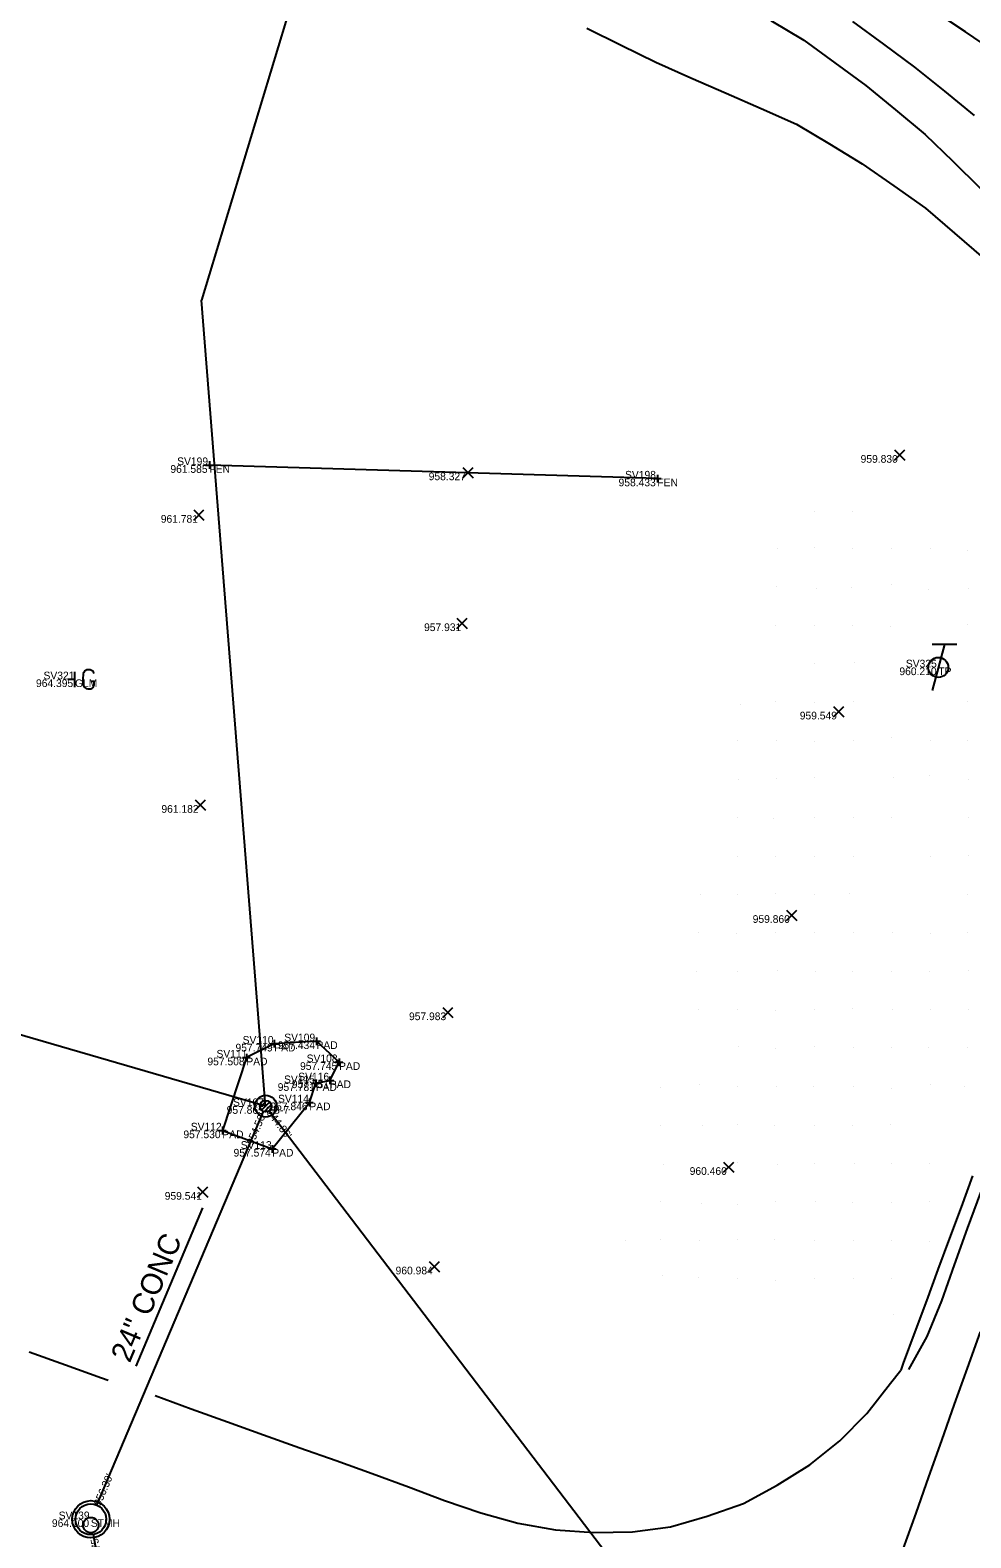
# Model space of a CAD drawing. Extents: x 2262025 to 2264532, y 740981 to 742724.
# Drawn here: x 2262920.9 to 2263043.2, y 741598.2 to 741794.3 of the extents above; entities that cross this region are included whole.
import ezdxf

# ---------------------------------------------------------------- set-up
doc = ezdxf.new("R2010")
doc.units = 0
for name, color, linetype in [('DR_X_Storm_Sewer', 7, 'Continuous'), ('DR_X_Text', 7, 'Continuous'), ('DT_X_Break_Line', 7, 'Continuous'), ('GE_X_Alignment_1000_Cardinal_Points', 7, 'Continuous'), ('GE_X_Alignment_100_Curve_Data', 7, 'Continuous'), ('GE_X_Alignment_500_Bearings', 7, 'Continuous'), ('GE_X_Alignment_500_Cardinal_Points', 7, 'Continuous'), ('Ground Shots', 7, 'Continuous'), ('HY_X_Spring_Cells', 7, 'Continuous'), ('RS_Raster1', 7, 'Continuous'), ('RW_X_CL', 7, 'Continuous'), ('RW_X_CL_1000_Distances', 7, 'Continuous'), ('RW_X_CL_100_Cardinal_Points', 7, 'Continuous'), ('RW_X_CL_100_Curve_Data', 7, 'Continuous'), ('RW_X_CL_100_Stations', 7, 'Continuous'), ('RW_X_CL_500_Curve_Data', 7, 'Continuous'), ('RW_X_CL_500_Stations', 7, 'Continuous'), ('SV_X_Control_Cells_Found', 7, 'Continuous'), ('SV_X_Text_Comment', 7, 'Continuous'), ('UT_X_Gas_Cells', 7, 'Continuous'), ('UT_X_Telecom_Cells', 7, 'Continuous')]:
    doc.layers.add(name, color=color, linetype=linetype)

msp = doc.modelspace()

# ---------------------------------------------------------------- linework, layer by layer
at = {"layer": 'DR_X_Storm_Sewer'}
for p, q in [((2262952, 741653.76), (2263353.07, 741127.49)), ((2262929.6, 741602.48), (2262951.25, 741653.67)), ((2262938.08, 741547.02), (2262929.17, 741598.66))]:
    msp.add_line(p, q, dxfattribs=at)
at = {"layer": 'DR_X_Text'}
msp.add_line((2262943.35, 741641.14), (2262934.65, 741620.56), dxfattribs=at)
at = {"layer": 'DT_X_Break_Line'}
msp.add_lwpolyline([(2263092.31, 741760.6), (2263084, 741766.16), (2263075.69, 741771.72), (2263067.37, 741777.28), (2263059.06, 741782.84), (2263050.77, 741788.43), (2263042.51, 741794.07), (2263034.2, 741799.62), (2263026.31, 741804.81)], dxfattribs=at)
at = {"layer": 'GE_X_Alignment_1000_Cardinal_Points'}
msp.add_lwpolyline([(2263002.45, 741735.97), (2262944.23, 741737.72)], dxfattribs=at)
at = {"layer": 'GE_X_Alignment_100_Curve_Data'}
for points in [[(2263017.19, 741795.56), (2263021.47, 741792.98), (2263025.51, 741790.04), (2263029.55, 741787.09), (2263033.41, 741783.91), (2263037.27, 741780.73), (2263040.85, 741777.24), (2263044.42, 741773.74)], [(2263044.43, 741643.14), (2263042.71, 741638.45), (2263041.05, 741633.73), (2263039.37, 741629.03), (2263037.49, 741624.39), (2263035.11, 741620.09)]]:
    msp.add_lwpolyline(points, dxfattribs=at)
at = {"layer": 'GE_X_Alignment_500_Bearings'}
for points in [[(2262920.8, 741622.42), (2262925.51, 741620.73), (2262930.21, 741619.04), (2262931.07, 741618.73)], [(2262937.16, 741616.72), (2262941.86, 741615.01), (2262946.56, 741613.3), (2262951.26, 741611.59), (2262955.98, 741609.93), (2262960.7, 741608.29), (2262965.4, 741606.6), (2262970.09, 741604.85), (2262974.77, 741603.09), (2262979.49, 741601.45), (2262984.3, 741600.11), (2262989.22, 741599.25), (2262994.2, 741598.92), (2262999.2, 741598.99), (2263004.15, 741599.63), (2263008.94, 741601.03), (2263013.64, 741602.69), (2263018.03, 741605.08), (2263022.27, 741607.72), (2263026.18, 741610.82), (2263029.67, 741614.38), (2263032.75, 741618.32), (2263034.09, 741620.03)]]:
    msp.add_lwpolyline(points, dxfattribs=at)
at = {"layer": 'GE_X_Alignment_500_Cardinal_Points'}
for p, q in [((2263033.26, 741738.36), (2263034.6, 741739.7)), ((2263033.26, 741739.7), (2263034.6, 741738.36)), ((2262977.17, 741736.09), (2262978.5, 741737.43)), ((2262977.17, 741737.43), (2262978.5, 741736.09)), ((2262942.19, 741730.56), (2262943.52, 741731.9)), ((2262942.19, 741731.9), (2262943.52, 741730.56)), ((2262976.4, 741716.48), (2262977.74, 741717.81)), ((2262976.4, 741717.81), (2262977.74, 741716.48)), ((2263025.33, 741704.98), (2263026.67, 741706.32)), ((2263025.33, 741706.32), (2263026.67, 741704.98)), ((2262942.38, 741692.85), (2262943.71, 741694.18)), ((2262942.38, 741694.18), (2262943.71, 741692.85)), ((2263019.23, 741678.52), (2263020.56, 741679.85)), ((2263019.23, 741679.85), (2263020.56, 741678.52)), ((2262974.56, 741665.87), (2262975.89, 741667.2)), ((2262974.56, 741667.2), (2262975.89, 741665.87)), ((2263011.05, 741645.75), (2263012.38, 741647.08)), ((2263011.05, 741647.08), (2263012.38, 741645.75)), ((2262942.7, 741642.52), (2262944.03, 741643.86)), ((2262942.7, 741643.86), (2262944.03, 741642.52)), ((2262972.8, 741632.82), (2262974.13, 741634.15)), ((2262972.8, 741634.15), (2262974.13, 741632.82))]:
    msp.add_line(p, q, dxfattribs=at)
at = {"layer": 'Ground Shots'}
for p, q in [((2263022.82, 741731.73), (2263022.82, 741731.73)), ((2263027.75, 741731.74), (2263027.75, 741731.74)), ((2263018.03, 741726.82), (2263018.03, 741726.82)), ((2263022.85, 741727), (2263022.85, 741727)), ((2263027.78, 741726.88), (2263027.78, 741726.88)), ((2263032.83, 741726.94), (2263032.83, 741726.94)), ((2263037.9, 741726.86), (2263037.9, 741726.86)), ((2263042.82, 741726.62), (2263042.82, 741726.62)), ((2263017.94, 741721.96), (2263017.94, 741721.96)), ((2263023.09, 741721.68), (2263023.09, 741721.68)), ((2263027.67, 741721.78), (2263027.67, 741721.78)), ((2263032.91, 741722.26), (2263032.91, 741722.26)), ((2263037.7, 741721.59), (2263037.7, 741721.59)), ((2263042.83, 741721.67), (2263042.83, 741721.67)), ((2263017.84, 741716.88), (2263017.84, 741716.88)), ((2263022.94, 741716.81), (2263022.94, 741716.81)), ((2263027.76, 741716.93), (2263027.76, 741716.93)), ((2263032.78, 741716.73), (2263032.78, 741716.73)), ((2263042.79, 741716.97), (2263042.79, 741716.97)), ((2263022.9, 741711.89), (2263022.9, 741711.89)), ((2263028.04, 741712.11), (2263028.04, 741712.11)), ((2263037.89, 741711.84), (2263037.89, 741711.84)), ((2263017.86, 741706.92), (2263017.86, 741706.92)), ((2263022.88, 741706.91), (2263022.88, 741706.91)), ((2263027.89, 741707), (2263027.89, 741707)), ((2263042.71, 741706.93), (2263042.71, 741706.93)), ((2263013.26, 741706.65), (2263013.26, 741706.65)), ((2263012.85, 741701.86), (2263012.85, 741701.86)), ((2263017.93, 741701.96), (2263017.93, 741701.96)), ((2263022.84, 741701.83), (2263022.84, 741701.83)), ((2263027.92, 741701.88), (2263027.92, 741701.88)), ((2263032.94, 741702.26), (2263032.94, 741702.26)), ((2263037.91, 741701.86), (2263037.91, 741701.86)), ((2263042.79, 741701.87), (2263042.79, 741701.87)), ((2263017.95, 741696.92), (2263017.95, 741696.92)), ((2263022.84, 741697.08), (2263022.84, 741697.08)), ((2263033.09, 741697.06), (2263033.09, 741697.06)), ((2263037.88, 741697.31), (2263037.88, 741697.31)), ((2263042.88, 741696.89), (2263042.88, 741696.89)), ((2263012.96, 741696.87), (2263012.96, 741696.87)), ((2263012.92, 741691.95), (2263012.92, 741691.95)), ((2263017.61, 741691.82), (2263017.61, 741691.82)), ((2263022.92, 741691.92), (2263022.92, 741691.92)), ((2263027.92, 741691.84), (2263027.92, 741691.84)), ((2263032.89, 741691.92), (2263032.89, 741691.92)), ((2263042.89, 741691.89), (2263042.89, 741691.89)), ((2263012.83, 741686.88), (2263012.83, 741686.88)), ((2263017.81, 741686.88), (2263017.81, 741686.88)), ((2263022.86, 741686.86), (2263022.86, 741686.86)), ((2263027.92, 741686.86), (2263027.92, 741686.86)), ((2263037.9, 741686.88), (2263037.9, 741686.88)), ((2263042.83, 741686.99), (2263042.83, 741686.99)), ((2263008.11, 741681.86), (2263008.11, 741681.86)), ((2263012.86, 741681.86), (2263012.86, 741681.86)), ((2263017.84, 741681.95), (2263017.84, 741681.95)), ((2263022.87, 741681.89), (2263022.87, 741681.89)), ((2263027.45, 741682.05), (2263027.45, 741682.05)), ((2263042.82, 741681.93), (2263042.82, 741681.93)), ((2263007.85, 741676.92), (2263007.85, 741676.92)), ((2263012.8, 741676.83), (2263012.8, 741676.83)), ((2263017.87, 741676.93), (2263017.87, 741676.93)), ((2263022.82, 741676.91), (2263022.82, 741676.91)), ((2263027.88, 741676.95), (2263027.88, 741676.95)), ((2263032.97, 741676.93), (2263032.97, 741676.93)), ((2263037.96, 741676.87), (2263037.96, 741676.87)), ((2263042.74, 741676.98), (2263042.74, 741676.98)), ((2263007.6, 741671.93), (2263007.6, 741671.93)), ((2263012.85, 741671.91), (2263012.85, 741671.91)), ((2263018.04, 741671.99), (2263018.04, 741671.99)), ((2263022.95, 741671.92), (2263022.95, 741671.92)), ((2263027.86, 741671.85), (2263027.86, 741671.85)), ((2263032.89, 741671.91), (2263032.89, 741671.91)), ((2263037.87, 741671.91), (2263037.87, 741671.91)), ((2263042.86, 741671.94), (2263042.86, 741671.94)), ((2263007.83, 741666.91), (2263007.83, 741666.91)), ((2263012.87, 741666.89), (2263012.87, 741666.89)), ((2263017.86, 741666.86), (2263017.86, 741666.86)), ((2263022.83, 741666.9), (2263022.83, 741666.9)), ((2263027.77, 741667.02), (2263027.77, 741667.02)), ((2263032.95, 741666.9), (2263032.95, 741666.9)), ((2263037.93, 741666.93), (2263037.93, 741666.93)), ((2263042.88, 741666.93), (2263042.88, 741666.93)), ((2263013.02, 741662.17), (2263013.02, 741662.17)), ((2263017.83, 741661.83), (2263017.83, 741661.83)), ((2263022.83, 741662.1), (2263022.83, 741662.1)), ((2263027.93, 741662.02), (2263027.93, 741662.02)), ((2263032.88, 741661.97), (2263032.88, 741661.97)), ((2263037.75, 741662), (2263037.75, 741662)), ((2263042.71, 741661.94), (2263042.71, 741661.94)), ((2263002.85, 741656.74), (2263002.85, 741656.74)), ((2263007.88, 741657.16), (2263007.88, 741657.16)), ((2263012.88, 741656.86), (2263012.88, 741656.86)), ((2263017.92, 741656.92), (2263017.92, 741656.92)), ((2263022.77, 741656.87), (2263022.77, 741656.87)), ((2263027.88, 741656.94), (2263027.88, 741656.94)), ((2263032.86, 741656.65), (2263032.86, 741656.65)), ((2263037.98, 741657.17), (2263037.98, 741657.17)), ((2263042.43, 741656.97), (2263042.43, 741656.97)), ((2263002.8, 741651.87), (2263002.8, 741651.87)), ((2263008.26, 741651.81), (2263008.26, 741651.81)), ((2263012.92, 741652), (2263012.92, 741652)), ((2263017.7, 741651.78), (2263017.7, 741651.78)), ((2263022.88, 741651.86), (2263022.88, 741651.86)), ((2263027.83, 741651.87), (2263027.83, 741651.87)), ((2263032.79, 741651.98), (2263032.79, 741651.98)), ((2263003.2, 741646.8), (2263003.2, 741646.8)), ((2263012.87, 741647.05), (2263012.87, 741647.05)), ((2263018.01, 741646.81), (2263018.01, 741646.81)), ((2263022.86, 741646.94), (2263022.86, 741646.94)), ((2263028.06, 741646.86), (2263028.06, 741646.86)), ((2263032.82, 741646.89), (2263032.82, 741646.89)), ((2263037.85, 741646.86), (2263037.85, 741646.86)), ((2263002.83, 741642.02), (2263002.83, 741642.02)), ((2263017.86, 741642.02), (2263017.86, 741642.02)), ((2263008.23, 741641.74), (2263008.23, 741641.74)), ((2263012.9, 741641.54), (2263012.9, 741641.54)), ((2263022.99, 741641.93), (2263022.99, 741641.93)), ((2263027.81, 741641.88), (2263027.81, 741641.88)), ((2263032.88, 741641.89), (2263032.88, 741641.89)), ((2263037.81, 741641.93), (2263037.81, 741641.93)), ((2262998.28, 741636.9), (2262998.28, 741636.9)), ((2263002.89, 741636.95), (2263002.89, 741636.95)), ((2263007.9, 741636.86), (2263007.9, 741636.86)), ((2263012.87, 741636.98), (2263012.87, 741636.98)), ((2263017.74, 741636.98), (2263017.74, 741636.98)), ((2263022.88, 741636.89), (2263022.88, 741636.89)), ((2263027.89, 741636.87), (2263027.89, 741636.87)), ((2263032.87, 741636.9), (2263032.87, 741636.9)), ((2263037.83, 741636.78), (2263037.83, 741636.78)), ((2263003.06, 741632.27), (2263003.06, 741632.27)), ((2263007.8, 741632.07), (2263007.8, 741632.07)), ((2263012.84, 741631.96), (2263012.84, 741631.96)), ((2263017.78, 741631.74), (2263017.78, 741631.74)), ((2263022.92, 741631.93), (2263022.92, 741631.93)), ((2263027.92, 741631.92), (2263027.92, 741631.92)), ((2263032.9, 741631.91), (2263032.9, 741631.91)), ((2263033.16, 741627.24), (2263033.16, 741627.24))]:
    msp.add_line(p, q, dxfattribs=at)
at = {"layer": 'RW_X_CL_1000_Distances'}
for points in [[(2263043.67, 741783.19), (2263039.8, 741786.36), (2263035.9, 741789.48), (2263031.88, 741792.46), (2263027.84, 741795.41)], [(2263034.39, 741596.73), (2263036.07, 741601.44), (2263037.74, 741606.15), (2263039.41, 741610.87), (2263041.09, 741615.58), (2263042.77, 741620.29), (2263044.45, 741624.99)]]:
    msp.add_lwpolyline(points, dxfattribs=at)
at = {"layer": 'RW_X_CL_100_Cardinal_Points'}
for p, q in [((2262944.23, 741738.22), (2262944.23, 741737.22)), ((2262943.73, 741737.72), (2262944.73, 741737.72)), ((2262944.23, 741737.72), (2262944.23, 741737.72)), ((2263002.45, 741736.47), (2263002.45, 741735.47)), ((2263001.95, 741735.97), (2263002.95, 741735.97)), ((2263002.45, 741735.97), (2263002.45, 741735.97)), ((2262952.16, 741662.47), (2262953.16, 741662.47)), ((2262952.66, 741662.97), (2262952.66, 741661.97)), ((2262952.66, 741662.47), (2262952.66, 741662.47)), ((2262957.65, 741662.79), (2262958.65, 741662.79)), ((2262958.15, 741663.29), (2262958.15, 741662.29)), ((2262958.15, 741662.79), (2262958.15, 741662.79)), ((2262948.53, 741660.67), (2262949.53, 741660.67)), ((2262949.03, 741661.17), (2262949.03, 741660.17)), ((2262949.03, 741660.67), (2262949.03, 741660.67)), ((2262960.58, 741660.07), (2262961.58, 741660.07)), ((2262961.08, 741660.57), (2262961.08, 741659.57)), ((2262961.08, 741660.07), (2262961.08, 741660.07)), ((2262958.05, 741657.84), (2262958.05, 741656.84)), ((2262959.38, 741657.7), (2262960.38, 741657.7)), ((2262959.88, 741658.2), (2262959.88, 741657.2)), ((2262959.88, 741657.7), (2262959.88, 741657.7)), ((2262957.55, 741657.34), (2262958.55, 741657.34)), ((2262958.05, 741657.34), (2262958.05, 741657.34)), ((2262956.72, 741654.83), (2262957.72, 741654.83)), ((2262957.22, 741655.33), (2262957.22, 741654.33)), ((2262957.22, 741654.83), (2262957.22, 741654.83)), ((2262945.41, 741651.19), (2262946.41, 741651.19)), ((2262945.91, 741651.69), (2262945.91, 741650.69)), ((2262945.91, 741651.19), (2262945.91, 741651.19)), ((2262951.9, 741648.8), (2262952.9, 741648.8)), ((2262952.4, 741649.3), (2262952.4, 741648.3)), ((2262952.4, 741648.8), (2262952.4, 741648.8))]:
    msp.add_line(p, q, dxfattribs=at)
at = {"layer": 'RW_X_CL_100_Curve_Data'}
for p, q in [((2262950.81, 741654.21), (2262951.69, 741655.1)), ((2262950.81, 741654.21), (2262951.69, 741655.1)), ((2262951, 741653.84), (2262952.07, 741654.9)), ((2262951, 741653.84), (2262952.07, 741654.9)), ((2262951.36, 741653.63), (2262952.27, 741654.54)), ((2262951.36, 741653.63), (2262952.27, 741654.54))]:
    msp.add_line(p, q, dxfattribs=at)
for centre, radius in [((2262951.55, 741654.36), 1.42), ((2262951.55, 741654.36), 1.42), ((2262951.54, 741654.36), 0.75), ((2262951.54, 741654.36), 0.75), ((2262951.55, 741654.36), 0.75), ((2262951.55, 741654.36), 0.75), ((2262928.82, 741600.63), 2.42), ((2262928.82, 741600.63), 2.42), ((2262928.82, 741600.63), 2), ((2262928.82, 741600.63), 2), ((2262928.82, 741599.88), 1), ((2262928.82, 741599.88), 1)]:
    msp.add_circle(centre, radius, dxfattribs=at)
at = {"layer": 'RW_X_CL_100_Stations'}
for p, q in [((2262951.55, 741655.78), (2262951.55, 741655.78)), ((2262951.55, 741655.78), (2262951.55, 741655.78)), ((2262951.54, 741654.36), (2262951.54, 741654.36)), ((2262951.54, 741654.36), (2262951.54, 741654.36)), ((2262951.54, 741654.36), (2262951.54, 741654.36)), ((2262951.54, 741654.36), (2262951.54, 741654.36)), ((2262951.54, 741654.36), (2262951.54, 741654.36)), ((2262951.54, 741654.36), (2262951.54, 741654.36)), ((2262951.55, 741652.94), (2262951.55, 741652.94)), ((2262951.55, 741652.94), (2262951.55, 741652.94)), ((2262928.82, 741602.63), (2262928.82, 741602.63)), ((2262928.82, 741602.63), (2262928.82, 741602.63)), ((2262928.82, 741600.63), (2262928.82, 741600.63)), ((2262928.82, 741600.63), (2262928.82, 741600.63)), ((2262928.82, 741600.63), (2262928.82, 741600.63)), ((2262928.82, 741600.63), (2262928.82, 741600.63)), ((2262928.82, 741599.88), (2262928.82, 741599.88)), ((2262928.82, 741599.88), (2262928.82, 741599.88)), ((2262928.82, 741598.63), (2262928.82, 741598.63)), ((2262928.82, 741598.63), (2262928.82, 741598.63))]:
    msp.add_line(p, q, dxfattribs=at)
for centre, radius in [((2262951.54, 741654.36), 0.75), ((2262951.54, 741654.36), 0.75), ((2262928.82, 741600.63), 2), ((2262928.82, 741600.63), 2)]:
    msp.add_circle(centre, radius, dxfattribs=at)
at = {"layer": 'RW_X_CL_500_Curve_Data'}
msp.add_lwpolyline([(2262961.08, 741660.07), (2262958.15, 741662.79), (2262952.66, 741662.47), (2262949.03, 741660.67), (2262945.91, 741651.19), (2262952.4, 741648.8), (2262957.22, 741654.83), (2262958.05, 741657.34), (2262959.88, 741657.7)], close=True, dxfattribs=at)
at = {"layer": 'RW_X_CL_500_Stations'}
for p, q in [((2262983.68, 741893.13), (2262943.22, 741759.19)), ((2262951.54, 741654.36), (2262943.22, 741759.19)), ((2262951.54, 741654.36), (2262896.64, 741670.33))]:
    msp.add_line(p, q, dxfattribs=at)
at = {"layer": 'SV_X_Control_Cells_Found'}
for points in [[(2262993.28, 741794.57), (2262997.76, 741792.35), (2263002.24, 741790.13), (2263006.81, 741788.11), (2263011.39, 741786.1), (2263015.96, 741784.08), (2263020.54, 741782.07), (2263024.82, 741779.49), (2263029.09, 741776.89), (2263033.19, 741774.03), (2263037.29, 741771.16), (2263041.07, 741767.9), (2263044.84, 741764.63)], [(2263043.42, 741645.3), (2263041.92, 741641.24), (2263040.42, 741637.18), (2263038.92, 741633.11), (2263037.42, 741629.05), (2263035.92, 741624.99), (2263034.42, 741620.93), (2263034.09, 741620.03)]]:
    msp.add_lwpolyline(points, dxfattribs=at)
at = {"layer": 'UT_X_Gas_Cells'}
for p, q in [((2262926.76, 741708.86), (2262926.76, 741710.86)), ((2262926.76, 741709.86), (2262925.81, 741709.86))]:
    msp.add_line(p, q, dxfattribs=at)
msp.add_lwpolyline([(2262929.23, 741710.61), (2262929.21, 741710.71), (2262929.16, 741710.81), (2262929.06, 741710.91), (2262928.92, 741711.03), (2262928.82, 741711.07), (2262928.74, 741711.09), (2262928.62, 741711.11), (2262928.39, 741711.11), (2262928.29, 741711.09), (2262928.23, 741711.07), (2262928.15, 741711.03), (2262927.99, 741710.91), (2262927.9, 741710.77), (2262927.84, 741710.61), (2262927.8, 741710.4), (2262927.76, 741710.08), (2262927.76, 741709.67), (2262927.78, 741709.33), (2262927.86, 741709.08), (2262927.97, 741708.84), (2262928.07, 741708.76), (2262928.19, 741708.68), (2262928.41, 741708.61), (2262928.62, 741708.61), (2262928.84, 741708.64), (2262928.92, 741708.68), (2262929, 741708.72), (2262929.08, 741708.8), (2262929.16, 741708.92), (2262929.23, 741709.1), (2262929.23, 741709.59), (2262928.82, 741709.59)], dxfattribs=at)
at = {"layer": 'UT_X_Telecom_Cells'}
for p, q in [((2263041.37, 741714.41), (2263038.17, 741714.41)), ((2263039.77, 741714.41), (2263038.17, 741708.41))]:
    msp.add_line(p, q, dxfattribs=at)
msp.add_circle((2263038.97, 741711.41), 1.3, dxfattribs=at)

# ---------------------------------------------------------------- texts
at = {"layer": 'DR_X_Text'}
msp.add_text('24" CONC', height=2.8, rotation=67.0771, dxfattribs=at).set_placement((2262933.88, 741620.86))
at = {"layer": 'HY_X_Spring_Cells'}
for s, p in [('959.830', (2263028.87, 741738.03)), ('961.585', (2262939.16, 741736.72)), ('958.327', (2262972.73, 741735.76)), ('958.433', (2262997.41, 741734.97)), ('961.781', (2262937.91, 741730.23)), ('957.931', (2262972.13, 741716.14)), ('960.210', (2263033.91, 741710.41)), ('964.395', (2262921.69, 741708.86)), ('959.549', (2263020.96, 741704.65)), ('961.182', (2262937.99, 741692.51)), ('959.860', (2263014.84, 741678.19)), ('957.983', (2262970.17, 741665.54)), ('957.749', (2262947.62, 741661.47)), ('957.434', (2262953.12, 741661.79)), ('957.508', (2262943.97, 741659.67)), ('957.745', (2262956.01, 741659.07)), ('957.751', (2262954.94, 741656.7)), ('957.781', (2262953.11, 741656.34)), ('957.865', (2262946.47, 741653.36)), ('957.865', (2262946.47, 741653.36)), ('957.846', (2262952.16, 741653.83)), ('957.530', (2262940.85, 741650.19)), ('957.574', (2262947.37, 741647.8)), ('960.460', (2263006.65, 741645.42)), ('959.541', (2262938.42, 741642.19)), ('960.984', (2262968.43, 741632.48)), ('964.100', (2262923.76, 741599.63)), ('964.100', (2262923.76, 741599.63))]:
    msp.add_text(s, height=1, dxfattribs=at).set_placement(p)
at = {"layer": 'RS_Raster1'}
for s, rotation, p in [("944.86'", 307.3107, (2262951.6, 741653.46)), ("954.56'", 67.0771, (2262949.91, 741649.21)), ("956.30'", 67.0771, (2262930.06, 741602.28)), ("956.75'", 99.7972, (2262930.45, 741594.18))]:
    msp.add_text(s, height=1, rotation=rotation, dxfattribs=at).set_placement(p)
at = {"layer": 'RW_X_CL'}
for s, p in [('FEN', (2262944.23, 741736.72)), ('FEN', (2263002.45, 741734.97)), ('TP', (2263038.97, 741710.41)), ('GLM', (2262926.76, 741708.86)), ('PAD', (2262952.66, 741661.47)), ('PAD', (2262958.15, 741661.79)), ('PAD', (2262949.03, 741659.67)), ('PAD', (2262961.08, 741659.07)), ('PAD', (2262959.88, 741656.7)), ('PAD', (2262958.05, 741656.34)), ('CB-7', (2262951.54, 741653.36)), ('CB-7', (2262951.54, 741653.36)), ('PAD', (2262957.22, 741653.83)), ('PAD', (2262945.91, 741650.19)), ('PAD', (2262952.4, 741647.8)), ('STMH', (2262928.82, 741599.63)), ('STMH', (2262928.82, 741599.63))]:
    msp.add_text(s, height=1, dxfattribs=at).set_placement(p)
at = {"layer": 'SV_X_Text_Comment'}
for s, p in [('SV199', (2262940.04, 741737.72)), ('SV198', (2262998.25, 741735.97)), ('SV321', (2262922.67, 741709.86)), ('SV325', (2263034.75, 741711.41)), ('SV109', (2262953.96, 741662.79)), ('SV111', (2262945.15, 741660.67)), ('SV110', (2262948.55, 741662.47)), ('SV108', (2262956.87, 741660.07)), ('SV115', (2262953.93, 741657.34)), ('SV116', (2262955.78, 741657.7)), ('SV114', (2262953.15, 741654.83)), ('SV107', (2262947.3, 741654.36)), ('SV107', (2262947.3, 741654.36)), ('SV112', (2262941.81, 741651.19)), ('SV113', (2262948.3, 741648.8)), ('SV139', (2262924.64, 741600.63)), ('SV139', (2262924.64, 741600.63))]:
    msp.add_text(s, height=1, dxfattribs=at).set_placement(p)

doc.saveas('drawing.dxf')
